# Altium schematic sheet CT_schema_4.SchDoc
size 400 x 269 mm
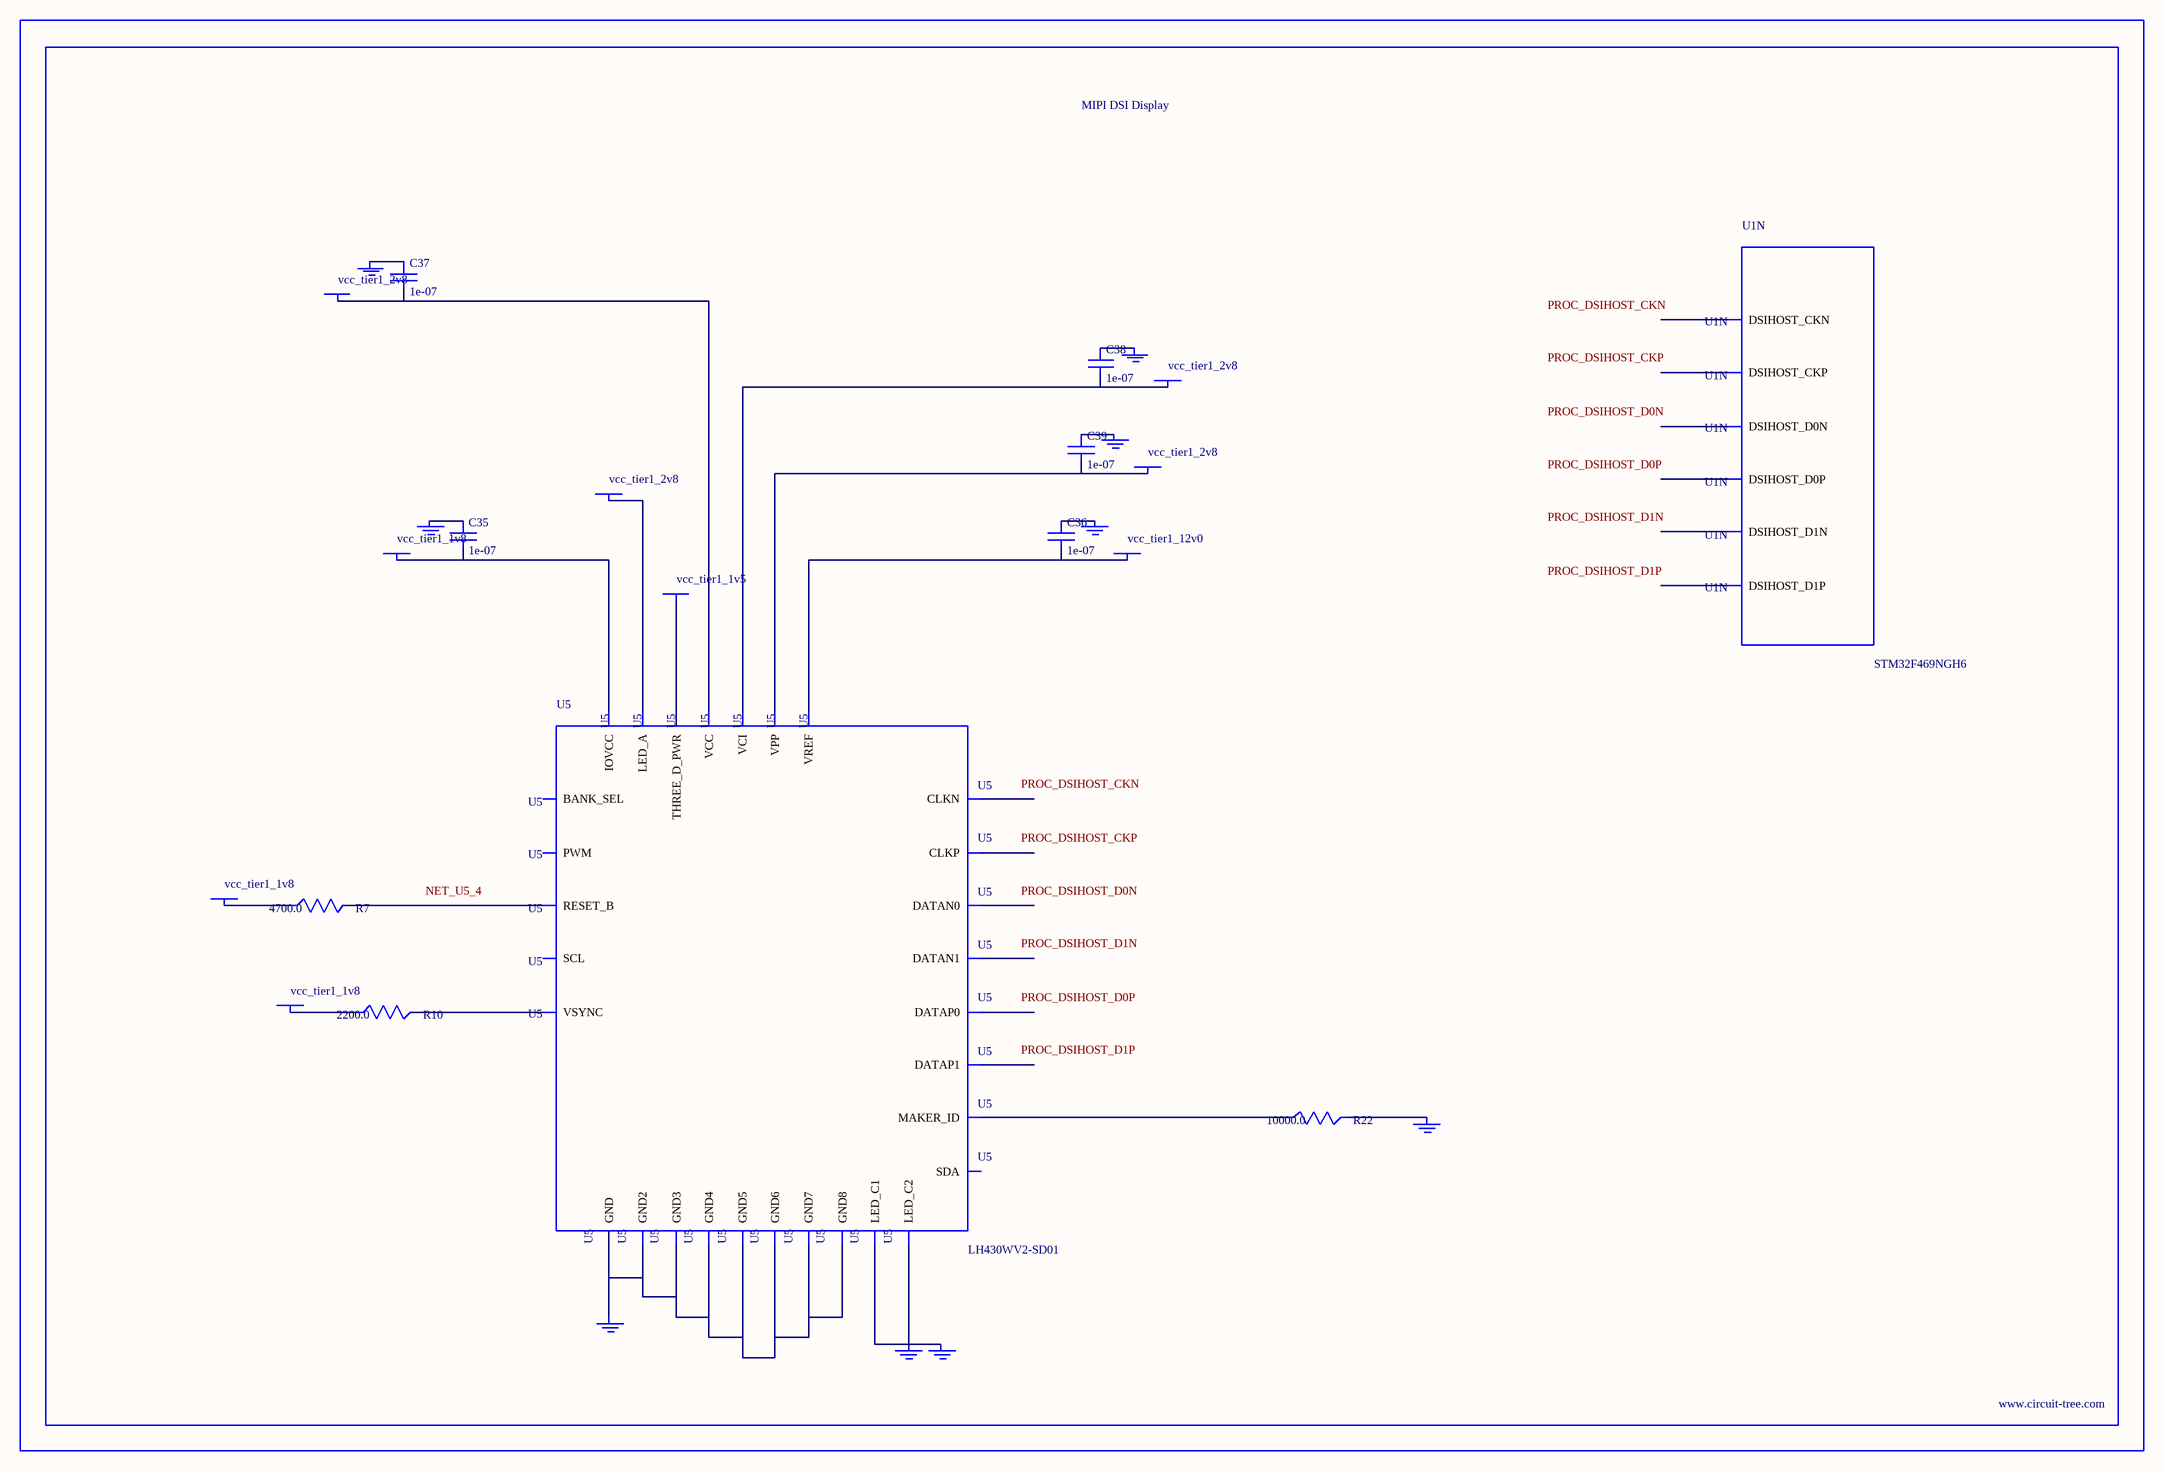
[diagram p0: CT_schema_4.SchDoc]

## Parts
BORDER3  (no value)
C35  1e-07  [C0402]
C36  1e-07  [C0402]
C37  1e-07  [C0402]
C38  1e-07  [C0402]
C39  1e-07  [C0402]
GND_INSTANCE_3_0  (no value)
GND_INSTANCE_3_1  (no value)
GND_INSTANCE_3_2  (no value)
GND_INSTANCE_3_3  (no value)
GND_INSTANCE_3_4  (no value)
GND_INSTANCE_3_5  (no value)
GND_INSTANCE_3_6  (no value)
GND_INSTANCE_3_7  (no value)
GND_INSTANCE_3_8  (no value)
POWER_INSTANCE_3_0  vcc_tier1_1v8
POWER_INSTANCE_3_1  vcc_tier1_2v8
POWER_INSTANCE_3_2  vcc_tier1_2v8
POWER_INSTANCE_3_3  vcc_tier1_2v8
POWER_INSTANCE_3_4  vcc_tier1_2v8
POWER_INSTANCE_3_5  vcc_tier1_12v0
POWER_INSTANCE_3_6  vcc_tier1_1v8
POWER_INSTANCE_3_7  vcc_tier1_1v8
POWER_INSTANCE_3_8  vcc_tier1_1v5
R7  4700.0  [R0603]
R10  2200.0  [R0603]
R22  10000.0  [R0603]
U1  STM32F469NGH6  [TFBGA216]  (part N of 16)
U5  LH430WV2-SD01  [LH430WV2-SD01]

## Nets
NetC35_1: C35.1 GND_INSTANCE_3_0.0(GND)
NetC35_2: C35.2 POWER_INSTANCE_3_0.0(PWR) U5.2(IOVCC)
NetC36_1: C36.1 GND_INSTANCE_3_7.0(GND)
NetC36_2: C36.2 POWER_INSTANCE_3_5.0(PWR) U5.30(VREF)
NetC37_1: C37.1 GND_INSTANCE_3_5.0(GND)
NetC37_2: C37.2 POWER_INSTANCE_3_3.0(PWR) U5.22(VCC)
NetC38_1: C38.1 GND_INSTANCE_3_4.0(GND)
NetC38_2: C38.2 POWER_INSTANCE_3_2.0(PWR) U5.21(VCI)
NetC39_1: C39.1 GND_INSTANCE_3_6.0(GND)
NetC39_2: C39.2 POWER_INSTANCE_3_4.0(PWR) U5.23(VPP)
NetGND_INSTANCE_3_1_0: GND_INSTANCE_3_1.0(GND) GND_INSTANCE_3_2.0(GND) U5.17(LED_C1) U5.18(LED_C2)
NetGND_INSTANCE_3_3_0: GND_INSTANCE_3_3.0(GND) R22.2
NetGND_INSTANCE_3_8_0: GND_INSTANCE_3_8.0(GND) U5.1(GND) U5.6(GND2) U5.9(GND3) U5.12(GND4) U5.15(GND5) U5.19(GND6) U5.24(GND7) U5.27(GND8)
NetPOWER_INSTANCE_3_1_0: POWER_INSTANCE_3_1.0(PWR) U5.16(LED_A)
NetPOWER_INSTANCE_3_6_0: POWER_INSTANCE_3_6.0(PWR) R7.1
NetPOWER_INSTANCE_3_7_0: POWER_INSTANCE_3_7.0(PWR) R10.1
NetPOWER_INSTANCE_3_8_0: POWER_INSTANCE_3_8.0(PWR) U5.29(THREE_D_PWR)
NetR7_2: R7.2 U5.4(RESET_B)
NetR10_2: R10.2 U5.5(VSYNC)
NetR22_1: R22.1 U5.20(MAKER_ID)

Not connected (* = marked no-connect by the designer): U1 F12(DSIHOST_D1P) F13(DSIHOST_D1N) H12(DSIHOST_CKP) H13(DSIHOST_CKN) J12(DSIHOST_D0P) J13(DSIHOST_D0N); U5 3(PWM) 7(DATAN0) 8(DATAP0) 10(DATAN1) 11(DATAP1) 13(CLKN) 14(CLKP) 25(SCL) 26(SDA) 28(BANK_SEL)

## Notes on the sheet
- Labels drawn without touching a wire or pin: NET_U5_4, PROC_DSIHOST_CKN, PROC_DSIHOST_CKP, PROC_DSIHOST_D0N, PROC_DSIHOST_D0P, PROC_DSIHOST_D1N, PROC_DSIHOST_D1P

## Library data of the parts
BORDER3 = BORDER_PAGE3
C35-C39 = C0402C104K3RACTU
GND_INSTANCE_3_0-GND_INSTANCE_3_8 = GND
POWER_INSTANCE_3_0-POWER_INSTANCE_3_8 = PWR
R7 = RC0603JR-074K7L
R10 = RC0603JR-072K2L
R22 = RC0603JR-0710KL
